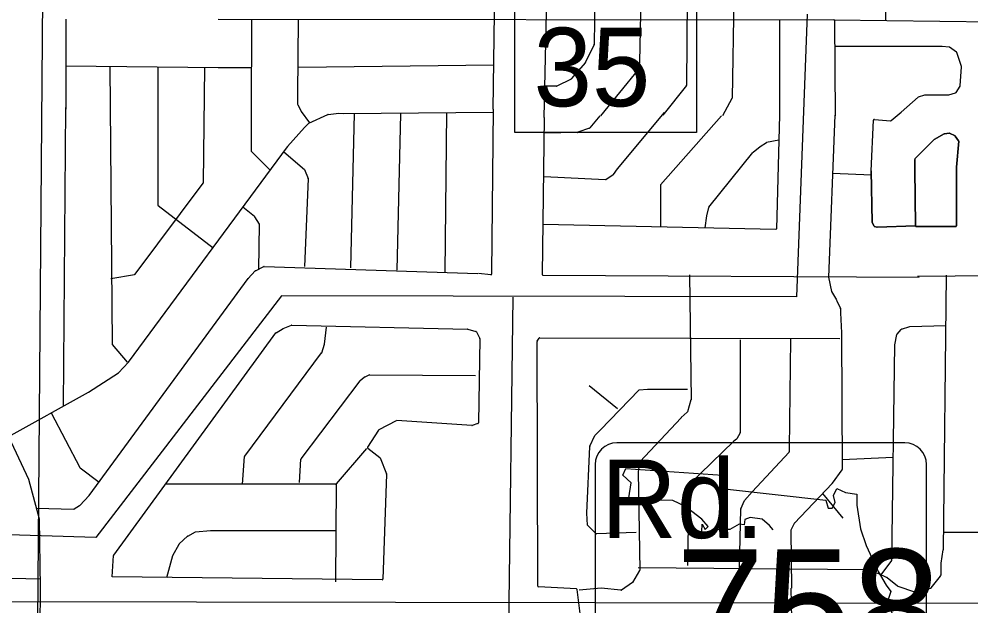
# Model space of a CAD drawing. Extents: x 408847 to 817539, y 923858 to 1151780.
# Drawn here: x 499864 to 505322, y 1078162 to 1081525 of the extents above; entities that cross this region are included whole.
import ezdxf

# ---------------------------------------------------------------- set-up
doc = ezdxf.new("R2010")
doc.units = 0
for name, color, linetype in [('Level 11', 7, 'Continuous'), ('Level 12', 7, 'Continuous'), ('Level 43', 7, 'Continuous'), ('Level 7', 7, 'Continuous'), ('Local Roads Improved', 7, 'Continuous'), ('Local Roads Paved', 7, 'Continuous'), ('Masks for Text', 7, 'Continuous'), ('Narrow River Creek and Branch and Slough', 7, 'Continuous'), ('Roadshields State Highways', 7, 'Continuous'), ('Section Lines', 7, 'Continuous')]:
    doc.layers.add(name, color=color, linetype=linetype)

msp = doc.modelspace()

# ---------------------------------------------------------------- linework, layer by layer
at = {"layer": 'Level 12'}
msp.add_line((502695.8, 1079931.8), (502659.7, 1077279.2), dxfattribs=at)
at = {"layer": 'Level 7'}
msp.add_line((483896.7, 1078211.6), (513104.2, 1078166.3), dxfattribs=at)
at = {"layer": 'Local Roads Improved'}
for p, q in [((501005.8, 1081524.8), (504535.8, 1081520.8)), ((501005.8, 1081524.8), (504535.8, 1081520.8)), ((504539.8, 1081516.8), (504543.9, 1080970.2)), ((505156.8, 1081368), (504540.9, 1081368)), ((505197.3, 1081364), (505157.2, 1081368)), ((505238.7, 1081335.6), (505199.2, 1081363.3)), ((505268.4, 1081252.9), (505240.2, 1081333.7)), ((505260.5, 1081141.4), (505268.7, 1081251.3)), ((505236.4, 1081104.3), (505259.9, 1081139.5)), ((504921.2, 1080991.4), (505019.9, 1081077.7)), ((505021.2, 1081078.5), (505057.1, 1081090.5)), ((505058.4, 1081090.7), (505193.7, 1081090.7)), ((505194.8, 1081090.9), (505234.2, 1081102.7)), ((504750.7, 1080654.6), (504763.8, 1080945.8)), ((504768.1, 1080949.6), (504861.6, 1080941.8)), ((504864.5, 1080942.8), (504921.2, 1080991.3)), ((505111.1, 1080833.7), (505001, 1080723.5)), ((505168.8, 1080866.8), (505112, 1080834.3)), ((505197.1, 1080871.1), (505170.2, 1080867.3)), ((505230.6, 1080855.2), (505199.5, 1080870.8)), ((505251.3, 1080827), (505232.1, 1080854)), ((505239.8, 1080676.8), (505252, 1080824.3)), ((504999.8, 1080720.7), (504999.8, 1080664.4)), ((505238.6, 1080339.6), (505239.8, 1080676.8)), ((504754.8, 1080361.2), (504750.7, 1080654.6)), ((504999.8, 1080664.4), (505003.9, 1080339.5)), ((504766.2, 1080337.4), (504755.2, 1080359.5)), ((504782.8, 1080331.8), (504768.8, 1080335.3)), ((505003.9, 1080339.5), (504783.9, 1080331.7)), ((505007.9, 1080335.6), (505234.6, 1080335.6))]:
    msp.add_line(p, q, dxfattribs=at)
for centre, start, end in [((504535.8, 1081516.8), 0.4306, 89.9337), ((504535.8, 1081516.8), 0.4306, 89.9337), ((505156.8, 1081364), 84.2868, 90), ((505196.9, 1081360), 54.9954, 84.2868), ((505236.4, 1081332.4), 19.2817, 54.9954), ((505264.7, 1081251.6), 355.7656, 19.2817), ((505233.1, 1081106.5), 286.7066, 326.3223), ((505256.5, 1081141.7), 326.3223, 355.7656), ((505022.5, 1081074.7), 108.443, 131.1992), ((505058.4, 1081086.7), 90, 108.443), ((505193.7, 1081094.7), 270, 286.7066), ((504767.8, 1080945.6), 85.2341, 177.4256), ((504861.9, 1080945.8), 265.2341, 310.6145), ((504918.6, 1080994.4), 310.6145, 311.1992), ((505114, 1080830.9), 119.7564, 135.0133), ((505170.7, 1080863.3), 98.1338, 119.7564), ((505197.7, 1080867.2), 63.4243, 98.1338), ((505228.8, 1080851.6), 35.5251, 63.4243), ((505248.1, 1080824.7), 355.2386, 35.5251), ((505003.8, 1080720.7), 135.0133, 180), ((504758.8, 1080361.3), 180.7954, 206.5544), ((504769.8, 1080339.2), 206.5544, 255.9575), ((504783.8, 1080335.7), 255.9575, 272.0342), ((505007.9, 1080339.6), 180.7204, 270), ((505234.6, 1080339.6), 270, 359.804)]:
    msp.add_arc(centre, 4, start, end, dxfattribs=at)
at = {"layer": 'Local Roads Paved'}
for p, q in [((503981, 1082768), (503952.3, 1081070.6)), ((503422.7, 1081276.7), (503455.8, 1082600.1)), ((502875.3, 1080961.2), (502909.7, 1082522.4)), ((503699.9, 1082480.4), (503691.6, 1081145.5)), ((503174.5, 1082385.1), (503162.1, 1081380.9)), ((504834.2, 1081517), (504838.4, 1081785.5)), ((500132.8, 1081524.8), (500132.8, 1081007.4)), ((501005.8, 1081524.8), (504535.8, 1081520.8)), ((501196.8, 1081524.6), (501194.9, 1080973.3)), ((501465.5, 1081524.3), (501461.7, 1081090.3)), ((504225.2, 1081521.1), (504223.6, 1080973.5)), ((504535.8, 1081520.8), (506480.9, 1081496.3)), ((504539.8, 1081516.8), (504543.9, 1080970.2)), ((503161.7, 1081379.2), (503112.7, 1081277)), ((505156.8, 1081368), (504540.9, 1081368)), ((505197.3, 1081364), (505157.2, 1081368)), ((505238.7, 1081335.6), (505199.2, 1081363.3)), ((505268.4, 1081252.9), (505240.2, 1081333.7)), ((503112.1, 1081276.1), (503030.2, 1081181.9)), ((503418.7, 1081240.5), (503422.7, 1081276.4)), ((500132.8, 1081255.9), (501005.8, 1081247.5)), ((500385.9, 1081253.5), (500398.1, 1079662.6)), ((500659.6, 1081250.8), (500659.6, 1080460.3)), ((500921.1, 1080586.3), (500929.5, 1081248.2)), ((501005.8, 1081247.5), (501198.9, 1081247.2)), ((502586.7, 1081260.1), (501465.8, 1081247.6)), ((503199.3, 1080970.2), (503417.8, 1081238.4)), ((505260.5, 1081141.4), (505268.7, 1081251.3)), ((503029, 1081181), (502947.8, 1081140.4)), ((502946, 1081139.9), (502879.3, 1081139.9)), ((503690.8, 1081143), (503555.1, 1080974.4)), ((505236.4, 1081104.3), (505259.9, 1081139.5)), ((501461.7, 1081090.3), (501461.7, 1081037.4)), ((503951.8, 1081068.7), (503898.5, 1080970.2)), ((504921.2, 1080991.4), (505019.9, 1081077.7)), ((505021.2, 1081078.5), (505057.1, 1081090.5)), ((505058.4, 1081090.7), (505193.7, 1081090.7)), ((505194.8, 1081090.9), (505234.2, 1081102.7)), ((500130.5, 1081018.5), (500118.2, 1079306.1)), ((501462.1, 1081035.6), (501482.2, 1080995.4)), ((501482.5, 1080994.8), (501529, 1080929.8)), ((502583.3, 1081008.8), (502573, 1080070.1)), ((501194.9, 1080973.3), (501194.9, 1080770.6)), ((501526.5, 1080928.7), (501635.6, 1080977.2)), ((501636.7, 1080977.5), (501697.4, 1080985.6)), ((501697.4, 1080985.6), (501726.2, 1080982.7)), ((501726.7, 1080982.7), (502583.1, 1080991)), ((501766.9, 1080098.6), (501787.4, 1080983.3)), ((502032.4, 1080086.3), (502052.9, 1080981.5)), ((502314.4, 1080988.4), (502306.2, 1080074.1)), ((502875.3, 1080961.2), (502863.1, 1080061.8)), ((503194, 1080969.4), (503137.5, 1080900.7)), ((503296.2, 1080667), (503565.8, 1080989.8)), ((503892.7, 1080969.4), (503542.3, 1080574)), ((504223.6, 1080973.5), (504207.4, 1080323.4)), ((504542.3, 1080973.5), (504505.6, 1080046)), ((504750.7, 1080654.6), (504763.8, 1080945.8)), ((504768.1, 1080949.6), (504861.6, 1080941.8)), ((504864.5, 1080942.8), (504921.2, 1080991.3)), ((501403.4, 1080793.6), (501501.2, 1080903.8)), ((501501.4, 1080903.9), (501525.3, 1080927.9)), ((503135.8, 1080899.5), (503068, 1080875.6)), ((503066.7, 1080875.3), (502875.3, 1080871.3)), ((504150.8, 1080818.3), (504220.1, 1080833.1)), ((505001, 1080723.5), (505111.1, 1080833.7)), ((505112, 1080834.3), (505168.8, 1080866.8)), ((505170.2, 1080867.3), (505197.1, 1080871.1)), ((505199.5, 1080870.8), (505230.6, 1080855.2)), ((505232.1, 1080854), (505251.3, 1080827)), ((500492.2, 1079559.2), (501403.1, 1080793.3)), ((504072.8, 1080761.2), (504113.2, 1080793.5)), ((504113.5, 1080793.7), (504149.5, 1080817.7)), ((505252, 1080824.3), (505239.8, 1080676.8)), ((501196, 1080767.8), (501304.3, 1080659.5)), ((501381.8, 1080764.5), (501500.5, 1080663.3)), ((503819.7, 1080446.8), (504072.2, 1080760.6)), ((504999.8, 1080664.4), (504999.8, 1080720.7)), ((505239.8, 1080676.8), (505238.6, 1080339.6)), ((501501.7, 1080661.7), (501521.4, 1080610.3)), ((502875.3, 1080621.9), (503225.4, 1080605.6)), ((503227.8, 1080606.2), (503271, 1080633.8)), ((503272.1, 1080634.8), (503296.1, 1080666.8)), ((504751, 1080629.9), (504529.1, 1080639.2)), ((504750.7, 1080654.6), (504754.8, 1080361.2)), ((505003.9, 1080339.5), (504999.8, 1080664.4)), ((500529.8, 1080063.1), (500920.3, 1080584)), ((501521.7, 1080608.7), (501501.3, 1080106.8)), ((503541.3, 1080571.3), (503541.3, 1080333.8)), ((500661.2, 1080457.1), (500978.3, 1080213)), ((501214.8, 1080393.3), (501147.1, 1080446.5)), ((503798.7, 1080327.6), (503806.9, 1080396.8)), ((503806.9, 1080397.3), (503818.9, 1080445.3)), ((501243.2, 1080348.9), (501215.7, 1080392.3)), ((501239.8, 1080090.4), (501243.9, 1080346.7)), ((504203.3, 1080319.5), (502867, 1080348.4)), ((504755.2, 1080359.5), (504766.2, 1080337.4)), ((504768.8, 1080335.3), (504782.8, 1080331.8)), ((504783.9, 1080331.7), (505003.9, 1080339.5)), ((505234.6, 1080335.6), (505007.9, 1080335.6)), ((501178.7, 1080037.4), (501218.9, 1080081.7)), ((501220, 1080082.6), (501267.5, 1080106.3)), ((501269.4, 1080106.7), (502494.1, 1080065.9)), ((502573, 1080070.1), (502573, 1080062.3)), ((500267.4, 1078794.6), (501178.4, 1080037.1)), ((500390, 1080037.3), (500527.3, 1080061.5)), ((502568.5, 1080058.3), (502499.4, 1080066)), ((502867.1, 1080057.8), (505024.4, 1080045.6)), ((503708.8, 1080058.1), (503717, 1079343.4)), ((504505.6, 1080045.1), (504521.8, 1079964.5)), ((505548.8, 1080053.9), (505014.8, 1080050.2)), ((505180.8, 1080057.5), (505162.8, 1078482.7)), ((504522.2, 1079963.2), (504550.4, 1079914.9)), ((504550.5, 1079914.6), (504574.6, 1079866.5)), ((504575, 1079864.8), (504575, 1079841.2)), ((504575, 1079841.1), (504579.1, 1079726.8)), ((501338.6, 1079727), (501378.5, 1079751)), ((501379, 1079751.2), (501427, 1079771.2)), ((501428.6, 1079771.5), (502436.5, 1079747.1)), ((501615.7, 1079661.7), (501628, 1079759.4)), ((502437.4, 1079746.9), (502484.2, 1079735.2)), ((504898.5, 1079719.6), (504921.6, 1079746.6)), ((504923.3, 1079747.8), (504970.8, 1079763.6)), ((504971.9, 1079763.8), (505177.5, 1079768.2)), ((500407, 1078452.2), (501337.4, 1079725.9)), ((502486.8, 1079733.1), (502506, 1079694.8)), ((502506.4, 1079692.9), (502498.3, 1079210.3)), ((502835, 1079678.9), (502845.6, 1079696.5)), ((502849, 1079698.4), (502850.8, 1079698.4)), ((502850.8, 1079698.4), (504570.9, 1079694.3)), ((503998.9, 1079686.1), (503998.9, 1079155.8)), ((504280.8, 1079064.8), (504289, 1079690.2)), ((504579.1, 1079726.7), (504583.2, 1078943.2)), ((504885.6, 1079657.9), (504897.6, 1079717.8)), ((500399.1, 1079660.1), (500483.9, 1079559)), ((501599.6, 1079612.8), (501615.6, 1079660.9)), ((502838.5, 1078275.6), (502834.5, 1079676.8)), ((504869.2, 1078424.3), (504885.5, 1079657.2)), ((501158.8, 1079020.4), (501599, 1079611.7)), ((500435.3, 1079498.1), (500492, 1079558.8)), ((500263.3, 1079387.3), (500434.5, 1079497.4)), ((501820.3, 1079453.1), (501844.1, 1079472.9)), ((501845, 1079473.5), (501872.3, 1079485.2)), ((501873.9, 1079485.5), (502481.9, 1079481.4)), ((501481.6, 1079004.1), (501819.7, 1079452.4)), ((503132.7, 1079424.5), (503296.2, 1079293.7)), ((499801.8, 1079131.2), (500263.3, 1079387.3)), ((503198.1, 1079171.1), (503417.7, 1079398.9)), ((503420.2, 1079400.1), (503467.6, 1079404.1)), ((503467.9, 1079404.1), (503696.6, 1079404.1)), ((503716.8, 1079342.2), (503696.9, 1079274.4)), ((500049, 1079267.9), (500213.9, 1078954.8)), ((503695.7, 1079272.5), (503659.9, 1079240.7)), ((502027.4, 1079223.3), (501927.2, 1079171.2)), ((502460.7, 1079195.3), (502029.5, 1079223.7)), ((502495.5, 1079206.6), (502462.2, 1079195.5)), ((503659.7, 1079240.4), (503423.7, 1078988.1)), ((501925.6, 1079169.8), (501862.8, 1079071.6)), ((503165.9, 1079138.9), (503198.1, 1079171.1)), ((503998.4, 1079153.8), (503978.9, 1079118.7)), ((499820.1, 1079101.2), (499917.9, 1078889.1)), ((503137.2, 1079077.8), (503165.1, 1079137.7)), ((503962, 1079105.5), (503705.9, 1078857.5)), ((503977.8, 1079117.4), (503962.3, 1079105.8)), ((501856.8, 1079064.5), (501682.3, 1078861.5)), ((501863.7, 1079066.3), (501933.5, 1079012)), ((503120.5, 1078693), (503136.8, 1079076.3)), ((504068.4, 1078815.5), (504279.8, 1079043.2)), ((504280.8, 1079045.9), (504280.8, 1079064.8)), ((501145.8, 1078860.1), (501158, 1079018.4)), ((501472.7, 1078868.3), (501480.8, 1079002)), ((501934.8, 1079010.3), (501970.9, 1078918.1)), ((503422.6, 1078985.9), (503414.7, 1078930.2)), ((504877, 1079012.2), (504582.9, 1078998.4)), ((500215, 1078953.5), (500323.4, 1078871)), ((503414.7, 1078929.6), (503422.8, 1078366.9)), ((504582.4, 1078940.8), (504526.1, 1078864.4)), ((499918.2, 1078888.5), (499979.2, 1078660.4)), ((501971.1, 1078916.5), (501950.9, 1078316.2)), ((501679.2, 1078860.1), (500704.9, 1078860.1)), ((501681.1, 1078300.1), (501685.2, 1078860.1)), ((503704.7, 1078854.7), (503696.6, 1078394.4)), ((504023.9, 1078766.9), (504068.4, 1078815.4)), ((504525.8, 1078864), (504309.8, 1078635.7)), ((500212.6, 1078737.9), (500267.4, 1078794.6)), ((504003.3, 1078718), (504023.2, 1078765.8)), ((504471.1, 1078806.2), (504587.3, 1078664.2)), ((499962.9, 1078721.4), (500178.4, 1078717.1)), ((500180.6, 1078717.8), (500211.8, 1078737.3)), ((503994.8, 1078382.2), (504003, 1078716.6)), ((499979.4, 1078659.4), (499986, 1078265.5)), ((503124.5, 1078624.9), (503120.5, 1078692.6)), ((500877, 1078586.3), (500961.8, 1078594.4)), ((500962.2, 1078594.4), (501677, 1078594.4)), ((503172.4, 1078575.5), (503125.6, 1078622.3)), ((504289, 1078593.5), (504293.1, 1078263.3)), ((504309.2, 1078634.8), (504289.4, 1078595.3)), ((500782.7, 1078517.2), (500830.9, 1078561.4)), ((500831.7, 1078561.9), (500875.5, 1078585.8)), ((503402.4, 1078582.5), (503175.3, 1078574.3)), ((505604.6, 1078582.2), (505163.9, 1078582.2)), ((500745.7, 1078451.8), (500781.9, 1078516.2)), ((500398.1, 1078328.7), (500406.2, 1078450.1)), ((500711.3, 1078325.4), (500745.3, 1078450.8)), ((505151.1, 1078407), (505162.8, 1078482.7)), ((503414.6, 1078382.2), (504717.5, 1078369.9)), ((504808, 1078340), (504868.4, 1078422)), ((505151.1, 1078342.2), (505151.1, 1078406.4)), ((499305.2, 1078332.9), (499985.1, 1078316.8)), ((501946.8, 1078312.4), (500398.1, 1078328.7)), ((503422.3, 1078364.8), (503382.4, 1078297.1)), ((504718.5, 1078369.7), (504787.2, 1078349.5)), ((504787.7, 1078349.3), (504840.1, 1078325.1)), ((504841, 1078324.6), (504901.3, 1078276.3)), ((505094.8, 1078264.8), (505146.8, 1078332.8)), ((505147.2, 1078333.5), (505150.7, 1078340.4)), ((503060, 1078259.7), (502842.3, 1078271.6)), ((503381.2, 1078295.8), (503317.8, 1078252.2)), ((504902.5, 1078275.7), (504998.9, 1078243.5)), ((499986, 1078265.5), (499958.2, 1075204.8)), ((503083.7, 1078104.2), (503063.7, 1078256.2)), ((503201.8, 1078263.6), (503075.5, 1078251.4)), ((503315.1, 1078251.5), (503202.6, 1078263.6)), ((504289, 1078263.6), (504293.1, 1078087.9)), ((505001, 1078243.4), (505092.5, 1078263.3))]:
    msp.add_line(p, q, dxfattribs=at)
msp.add_lwpolyline([(502583.3, 1081008.8), (502603.5, 1082518.3)], dxfattribs=at)
for centre, start, end in [((504535.8, 1081516.8), 0.4306, 89.9337), ((503158.1, 1081380.9), 334.3694, 359.293), ((505156.8, 1081364), 84.2868, 90), ((505196.9, 1081360), 54.9954, 84.2868), ((505236.4, 1081332.4), 19.2817, 54.9954), ((503109, 1081278.8), 319.0041, 334.3694), ((503418.7, 1081276.8), 353.6627, 358.5686), ((503414.7, 1081240.9), 320.8198, 353.6627), ((505264.7, 1081251.6), 355.7656, 19.2817), ((503027.2, 1081184.6), 296.5757, 319.0041), ((502946, 1081143.9), 270, 296.5757), ((503687.6, 1081145.5), 321.1832, 359.6454), ((505233.1, 1081106.5), 286.7066, 326.3223), ((505256.5, 1081141.7), 326.3223, 355.7656), ((501465.7, 1081090.3), 179.4907, 180), ((503948.3, 1081070.6), 331.5682, 359.0312), ((505022.5, 1081074.7), 108.443, 131.1992), ((505058.4, 1081086.7), 90, 108.443), ((505193.7, 1081094.7), 270, 286.7066), ((501465.7, 1081037.4), 180, 206.5544), ((501485.8, 1080997.1), 206.5544, 215.5251), ((501637.2, 1080973.5), 97.5981, 113.9724), ((501726.6, 1080986.7), 264.2007, 270.5592), ((504767.8, 1080945.6), 85.2341, 177.4256), ((504861.9, 1080945.8), 265.2341, 310.6145), ((504918.6, 1080994.4), 310.6145, 311.1992), ((501504.2, 1080901.1), 135.0134, 138.3797), ((501528.1, 1080925), 113.9724, 135.0134), ((503134.4, 1080903.3), 289.4484, 320.5406), ((503066.6, 1080879.3), 271.2194, 289.4484), ((505114, 1080830.9), 119.7564, 135.0133), ((505170.7, 1080863.3), 98.1338, 119.7564), ((505197.7, 1080867.2), 63.4243, 98.1338), ((505228.8, 1080851.6), 35.5251, 63.4243), ((501406.3, 1080791), 138.3797, 143.5702), ((504115.7, 1080790.4), 123.7024, 128.6728), ((504151.7, 1080814.4), 102.1002, 123.7024), ((505248.1, 1080824.7), 355.2386, 35.5251), ((501198.9, 1080770.6), 180, 224.9866), ((504075.3, 1080758), 128.6728, 141.1722), ((505003.8, 1080720.7), 135.0133, 180), ((501497.9, 1080660.3), 21.0286, 49.5607), ((503268.9, 1080637.2), 302.4833, 323.1429), ((503299.3, 1080664.4), 140.1363, 143.1429), ((500917.1, 1080586.4), 323.1429, 359.2797), ((501517.7, 1080608.9), 357.6733, 21.0286), ((503225.6, 1080609.6), 267.3358, 302.4833), ((503545.3, 1080571.3), 138.4531, 180), ((500663.6, 1080460.3), 180, 232.4185), ((503810.8, 1080396.4), 165.97, 173.2933), ((503822.8, 1080444.3), 141.1722, 165.97), ((501212.3, 1080390.2), 32.4591, 51.8298), ((501239.9, 1080346.8), 359.091, 32.4591), ((504758.8, 1080361.3), 180.7954, 206.5544), ((504203.4, 1080323.5), 268.7617, 358.5686), ((504769.8, 1080339.2), 206.5544, 255.9575), ((504783.8, 1080335.7), 255.9575, 272.0342), ((505007.9, 1080339.6), 180.7204, 270), ((505234.6, 1080339.6), 270, 359.804), ((501221.8, 1080079), 116.5757, 137.7396), ((501269.3, 1080102.7), 88.09, 116.5757), ((502577, 1080070.1), 179.3691, 180), ((500526.6, 1080065.5), 280.0126, 323.1429), ((501181.6, 1080034.7), 137.7396, 143.7507), ((502569, 1080062.3), 263.6569, 0), ((502867.1, 1080061.8), 179.2226, 269.6749), ((504509.6, 1080045.9), 177.7306, 191.3048), ((504525.7, 1079965.2), 191.3048, 210.2448), ((504547, 1079912.8), 26.5544, 30.2448), ((504571, 1079864.8), 360, 26.5544), ((504579, 1079841.2), 180, 182.0445), ((501380.5, 1079747.5), 112.6293, 120.9755), ((501428.5, 1079767.5), 88.6078, 112.6293), ((502436.4, 1079743.1), 75.9575, 88.6078), ((504924.6, 1079744), 108.443, 139.4119), ((504972, 1079759.8), 91.2194, 108.443), ((501340.6, 1079723.6), 120.9755, 143.8545), ((502483.2, 1079731.3), 26.5544, 75.9575), ((502502.4, 1079693), 359.0376, 26.5544), ((502849, 1079694.4), 90, 149.048), ((502850.8, 1079694.4), 89.8638, 90), ((504575.1, 1079726.6), 0.2983, 2.0445), ((504901.5, 1079717), 139.4119, 168.6952), ((500402.1, 1079662.7), 180.4417, 220.0171), ((501611.8, 1079662.2), 341.5731, 352.8783), ((502838.5, 1079676.9), 149.048, 180.1665), ((504889.5, 1079657.1), 168.6952, 179.2415), ((501595.8, 1079614.1), 323.333, 341.5731), ((500489, 1079561.6), 316.9883, 323.5702), ((500432.3, 1079500.8), 302.7474, 316.9883), ((501846.6, 1079469.8), 113.2083, 129.8187), ((501873.9, 1079481.5), 89.6153, 113.2083), ((501822.9, 1079450), 129.8187, 142.9766), ((503420.6, 1079396.1), 94.7659, 136.055), ((503467.9, 1079400.1), 90, 94.7659), ((503713, 1079343.3), 343.6177, 0.6545), ((503693.1, 1079275.5), 311.6468, 343.6177), ((502029.2, 1079219.8), 86.22, 117.4854), ((502460.9, 1079199.2), 266.22, 288.443), ((502494.3, 1079210.4), 288.443, 359.0376), ((503662.6, 1079237.7), 131.6468, 136.9225), ((501929, 1079167.6), 117.4854, 147.3741), ((503195.2, 1079173.9), 315.0134, 316.055), ((503994.9, 1079155.8), 330.9567, 0), ((503168.7, 1079136.1), 135.0134, 154.9933), ((503964.7, 1079102.6), 126.8827, 134.0893), ((503975.4, 1079120.6), 306.8827, 330.9567), ((501866.2, 1079069.5), 147.3741, 232.1121), ((503140.8, 1079076.1), 154.9933, 177.5645), ((504276.8, 1079045.9), 317.1344, 0), ((504284.8, 1079064.8), 179.2514, 180), ((501162, 1079018), 143.333, 175.6033), ((501484.8, 1079001.7), 142.9766, 176.5334), ((501931.1, 1079008.8), 21.3616, 52.1121), ((503426.6, 1078985.3), 136.9225, 171.8736), ((500217.4, 1078956.7), 207.7794, 232.7523), ((503418.7, 1078929.7), 171.8736, 180.8299), ((504579.2, 1078943.2), 323.6284, 0.2983), ((499914.3, 1078887.4), 14.9884, 24.765), ((501967.1, 1078916.6), 358.066, 21.3616), ((501679.2, 1078864.1), 270, 319.3177), ((503708.7, 1078854.6), 134.0893, 178.9865), ((504071.3, 1078812.7), 137.1344, 137.5029), ((504522.9, 1078866.8), 316.5899, 323.6284), ((504026.9, 1078764.2), 137.5029, 157.3896), ((500178.5, 1078721.1), 268.8762, 302.0174), ((500209.7, 1078740.7), 302.0174, 315.9736), ((504007, 1078716.5), 157.3896, 178.6035), ((499975.4, 1078659.3), 0.9644, 14.9884), ((503124.5, 1078692.9), 177.5645, 183.3649), ((500962.2, 1078590.4), 90, 95.4429), ((503128.5, 1078625.1), 183.3649, 224.9866), ((504293, 1078593.5), 153.4456, 180.707), ((504312.7, 1078633), 136.5899, 153.4456), ((500833.6, 1078558.4), 118.6217, 132.5237), ((500877.4, 1078582.3), 95.4429, 118.6217), ((503175.2, 1078578.3), 224.9866, 272.0464), ((500785.4, 1078514.2), 132.5237, 150.6537), ((500410.2, 1078449.8), 143.8545, 176.1854), ((500749.2, 1078449.8), 150.6537, 164.841), ((504865.2, 1078424.4), 323.6284, 359.2415), ((505155.1, 1078406.4), 171.2709, 180), ((503418.8, 1078366.9), 329.5461, 0.8299), ((504717.4, 1078365.9), 73.6032, 89.4609), ((504786.1, 1078345.7), 65.2147, 73.6032), ((504838.5, 1078321.5), 51.3272, 65.2147), ((505143.6, 1078335.2), 322.6075, 333.4456), ((505147.1, 1078342.2), 333.4456, 0), ((501946.9, 1078316.4), 269.3966, 358.066), ((502842.5, 1078275.6), 180.1665, 266.8764), ((503379, 1078299.1), 304.521, 329.5461), ((504903.8, 1078279.5), 231.3272, 251.557), ((503059.7, 1078255.7), 7.4924, 86.8764), ((503202.2, 1078259.6), 83.8817, 95.5301), ((503315.5, 1078255.5), 263.8817, 304.521), ((505000.2, 1078247.3), 251.557, 282.2703), ((505091.6, 1078267.2), 282.2703, 322.6075)]:
    msp.add_arc(centre, 4, start, end, dxfattribs=at)
at = {"layer": 'Masks for Text'}
msp.add_lwpolyline([(502707.1, 1081809.7), (503748.5, 1081809.7), (503748.5, 1080874.5), (502707.1, 1080874.5)], close=True, dxfattribs=at)
at = {"layer": 'Narrow River Creek and Branch and Slough'}
for p, q in [((504383.5, 1081553.5), (504321.4, 1079933.8)), ((501368.5, 1079937.8), (500305.4, 1078554.5)), ((504321.4, 1079933.8), (501368.5, 1079937.8)), ((500305.4, 1078554.5), (499216.3, 1078586.5))]:
    msp.add_line(p, q, dxfattribs=at)
at = {"layer": 'Roadshields State Highways'}
for p, q in [((504942.5, 1079097.1), (503292.5, 1079097.1)), ((503167.5, 1078972.1), (503167.5, 1077322.1)), ((505067.5, 1077322.1), (505067.5, 1078972.1))]:
    msp.add_line(p, q, dxfattribs=at)
for points in [[(504187.2, 1078598), (504167.5, 1078623.4), (504124.6, 1078659.6), (504055.4, 1078669.5), (504025.7, 1078656.3), (504022.4, 1078626.7), (503992.7, 1078630), (503940, 1078600.3), (503880.7, 1078600.3), (503804.8, 1078580.5), (503778.5, 1078587.1), (503781.8, 1078630), (503798.3, 1078600.3), (503814.7, 1078616.8), (503778.5, 1078659.6), (503722.4, 1078702.5), (503686.2, 1078732.2), (503613.7, 1078765.2), (503537.8, 1078768.5), (503382.9, 1078765.2), (503359.8, 1078781.7), (503373, 1078867.4), (503326.9, 1078910.3), (503343.3, 1078949.9)], [(503343.3, 1078949.9), (503897.1, 1078910.3), (503926.8, 1078831.1), (504490.5, 1078768.5), (504503.7, 1078722.3), (504526.8, 1078722.3), (504543.3, 1078755.3), (504533.4, 1078794.9), (504553.1, 1078834.4), (504602.6, 1078811.4), (504668.5, 1078801.5), (504668.5, 1078738.8), (504688.3, 1078603.6), (504721.3, 1078507.9), (504790.5, 1078359.5), (504836.6, 1078280.3), (504863, 1078244.1), (504843.2, 1078188), (504869.6, 1078118.7)]]:
    msp.add_lwpolyline(points, dxfattribs=at)
for centre, start, end in [((503292.5, 1078972.1), 90, 180), ((504942.5, 1078972.1), 0, 90)]:
    msp.add_arc(centre, 125, start, end, dxfattribs=at)
at = {"layer": 'Section Lines'}
msp.add_line((500020.7, 1084213.2), (499970.7, 1078062.7), dxfattribs=at)

# ---------------------------------------------------------------- texts
at = {"layer": 'Level 11'}
msp.add_text('Rd.', height=450, rotation=360, dxfattribs=at).set_placement((503201.1, 1078550.8))
at = {"layer": 'Level 43'}
msp.add_text('35', height=450, rotation=360, dxfattribs=at).set_placement((502814.3, 1081024.8))
at = {"layer": 'Roadshields State Highways'}
msp.add_text('758', height=680, dxfattribs=at).set_placement((503630.7, 1077807.1))

doc.saveas('drawing.dxf')
